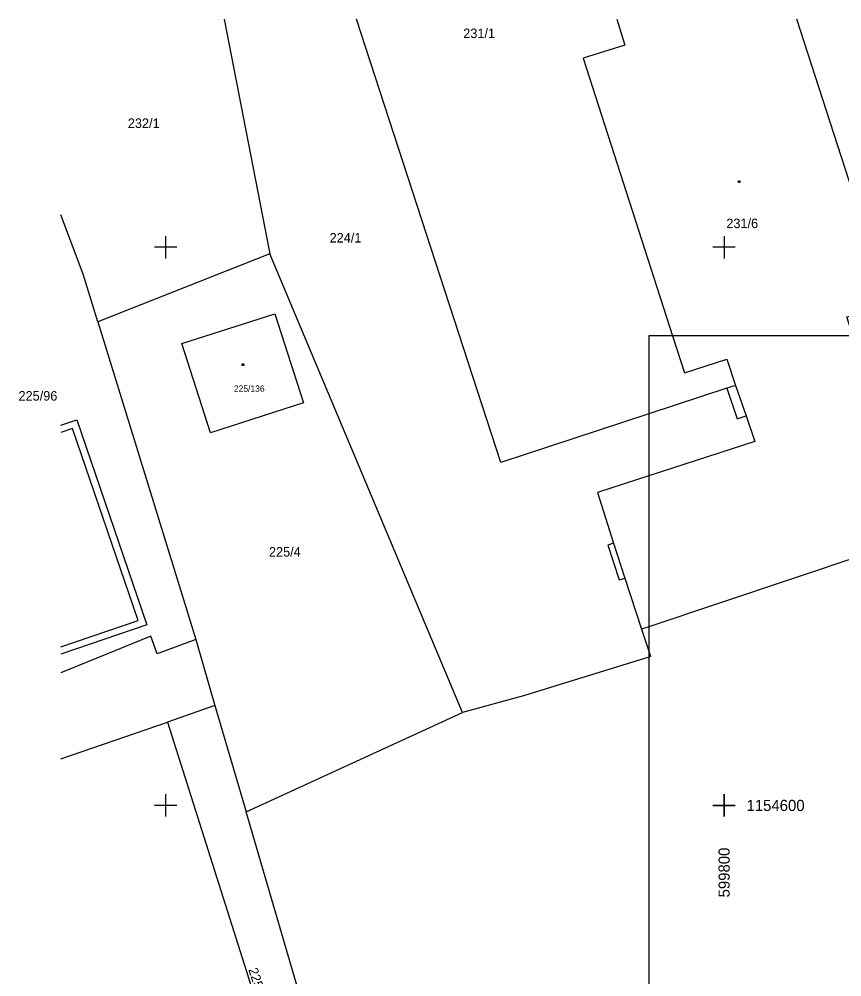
# Model space of a CAD drawing. Extents: x -599866 to -590076, y -1178039 to -1154526.
# Drawn here: x -599863.1 to -599789.5, y -1154615.4 to -1154529.6 of the extents above; entities that cross this region are included whole.
import ezdxf

# ---------------------------------------------------------------- set-up
doc = ezdxf.new("R2010")
doc.units = 0
for name, color, linetype in [('KN', 7, 'Continuous'), ('Rám', 7, 'Continuous'), ('Vrstva 5', 7, 'Continuous')]:
    doc.layers.add(name, color=color, linetype=linetype)

msp = doc.modelspace()

# ---------------------------------------------------------------- linework, layer by layer
at = {"layer": 'KN'}
for p, q in [((-599844.746, -1154529.575), (-599840.68, -1154550.58)), ((-599840.68, -1154550.58), (-599856.06, -1154556.68)), ((-599823.43, -1154591.68), (-599840.68, -1154550.58)), ((-599856.06, -1154556.68), (-599847.31, -1154585.15)), ((-599799.76, -1154562.64), (-599806.74, -1154564.93)), ((-599798.97, -1154562.38), (-599799.76, -1154562.64)), ((-599798.97, -1154562.38), (-599798.03, -1154565.1)), ((-599806.74, -1154564.93), (-599820, -1154569.28)), ((-599779.03, -1154574.73), (-599806.74, -1154583.989)), ((-599809.89, -1154576.51), (-599808.88, -1154579.63)), ((-599806.74, -1154583.989), (-599807.4, -1154584.21)), ((-599847.31, -1154585.15), (-599845.59, -1154591.05)), ((-599845.59, -1154591.05), (-599849.84, -1154592.53)), ((-599845.59, -1154591.05), (-599842.8, -1154600.57)), ((-599842.8, -1154600.57), (-599823.43, -1154591.68)), ((-599849.84, -1154592.53), (-599834.91, -1154639.59)), ((-599832.92, -1154634.27), (-599842.8, -1154600.57))]:
    msp.add_line(p, q, dxfattribs=at)
for points in [[(-599820, -1154569.28), (-599832.901, -1154529.575)], [(-599809.595, -1154529.575), (-599808.88, -1154531.9), (-599812.62, -1154533.06), (-599804.615, -1154557.95)], [(-599788.477, -1154557.95), (-599789.01, -1154556.24), (-599785.17, -1154555.3), (-599793.491, -1154529.575)], [(-599856.06, -1154556.68), (-599857.37, -1154552.41), (-599859.382, -1154547.112)], [(-599848.54, -1154558.63), (-599840.23, -1154555.97), (-599837.66, -1154563.94), (-599845.97, -1154566.63), (-599848.54, -1154558.63)], [(-599804.615, -1154557.95), (-599803.55, -1154561.26), (-599799.77, -1154560.04), (-599798.97, -1154562.38)], [(-599799.76, -1154562.64), (-599798.83, -1154565.37), (-599798.03, -1154565.1)], [(-599859.382, -1154565.952), (-599857.95, -1154565.47), (-599851.68, -1154583.83), (-599859.382, -1154586.444)], [(-599798.03, -1154565.1), (-599797.25, -1154567.39), (-599806.74, -1154570.479)], [(-599859.382, -1154585.807), (-599852.45, -1154583.45), (-599858.33, -1154566.24), (-599859.382, -1154566.593)], [(-599806.74, -1154570.479), (-599811.35, -1154571.98), (-599809.89, -1154576.51), (-599810.41, -1154576.68), (-599809.41, -1154579.8), (-599808.88, -1154579.63), (-599807.4, -1154584.21)], [(-599807.4, -1154584.21), (-599806.74, -1154586.182)], [(-599847.31, -1154585.15), (-599850.76, -1154586.42), (-599851.33, -1154584.84), (-599859.382, -1154588.12)], [(-599806.74, -1154586.182), (-599806.58, -1154586.66), (-599806.74, -1154586.71)], [(-599806.74, -1154586.71), (-599817.96, -1154590.19), (-599823.43, -1154591.68)], [(-599859.382, -1154595.835), (-599849.84, -1154592.53)]]:
    msp.add_lwpolyline(points, dxfattribs=at)
for centre in [(-599798.653, -1154544.13), (-599843.073, -1154560.52)]:
    msp.add_circle(centre, 0.0875, dxfattribs=at)
at = {"layer": 'Rám'}
for points in [[(-599701.74, -1154557.95), (-599806.74, -1154557.95)], [(-599806.74, -1154557.95), (-599806.74, -1154706.45)]]:
    msp.add_lwpolyline(points, dxfattribs=at)
at = {"layer": 'Vrstva 5'}
for p, q in [((-599850, -1154549), (-599850, -1154551)), ((-599800, -1154549), (-599800, -1154551)), ((-599849, -1154550), (-599851, -1154550)), ((-599799, -1154550), (-599801, -1154550)), ((-599850, -1154599), (-599850, -1154601)), ((-599800, -1154599), (-599800, -1154601)), ((-599800, -1154601), (-599800, -1154599)), ((-599849, -1154600), (-599851, -1154600)), ((-599799, -1154600), (-599801, -1154600)), ((-599801, -1154600), (-599799, -1154600))]:
    msp.add_line(p, q, dxfattribs=at)

# ---------------------------------------------------------------- texts
at = {"layer": 'KN'}
for s, height, p in [('231/1', 0.85, (-599823.354, -1154531.27)), ('232/1', 0.85, (-599853.383, -1154539.32)), ('231/6', 0.85, (-599799.8, -1154548.29)), ('224/1', 0.85, (-599835.317, -1154549.58)), ('225/96', 0.85, (-599863.17, -1154563.74)), ('225/136', 0.57, (-599843.892, -1154562.95)), ('225/4', 0.85, (-599840.749, -1154577.71))]:
    msp.add_text(s, height=height, dxfattribs=at).set_placement(p)
msp.add_text('225/26', height=0.85, rotation=288, dxfattribs=at).set_placement((-599842.601, -1154614.696))
at = {"layer": 'Vrstva 5'}
msp.add_text('1154600', height=1, dxfattribs=at).set_placement((-599798, -1154600.5))
msp.add_text('599800', height=1, rotation=90, dxfattribs=at).set_placement((-599799.5, -1154608.24))

doc.saveas('drawing.dxf')
